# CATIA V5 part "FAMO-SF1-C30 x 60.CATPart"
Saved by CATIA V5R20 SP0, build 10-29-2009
Part number: FAMO-SF1-C30 x 60
Definition: NONE
Nomenclature: FAMO-SF1-C30 x 60
Source: Unknown
Description: FAMO-SF1-C30 x 60
Bounding box of the stored display mesh (mm): x -34 to 26, y -26.5 to 26.5, z -26.5 to 26.5
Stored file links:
  C:\Users\Utente\Desktop\IO LAVORO\3D X SITO CF\X SITO\FAMO\FAMO-SF1-C30 x 60.CATPart
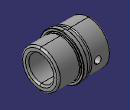
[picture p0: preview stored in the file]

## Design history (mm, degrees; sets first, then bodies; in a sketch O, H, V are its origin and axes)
Body1 "FAMO-SF1-C30 x 60" (main body)
  Solid1: solid without history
